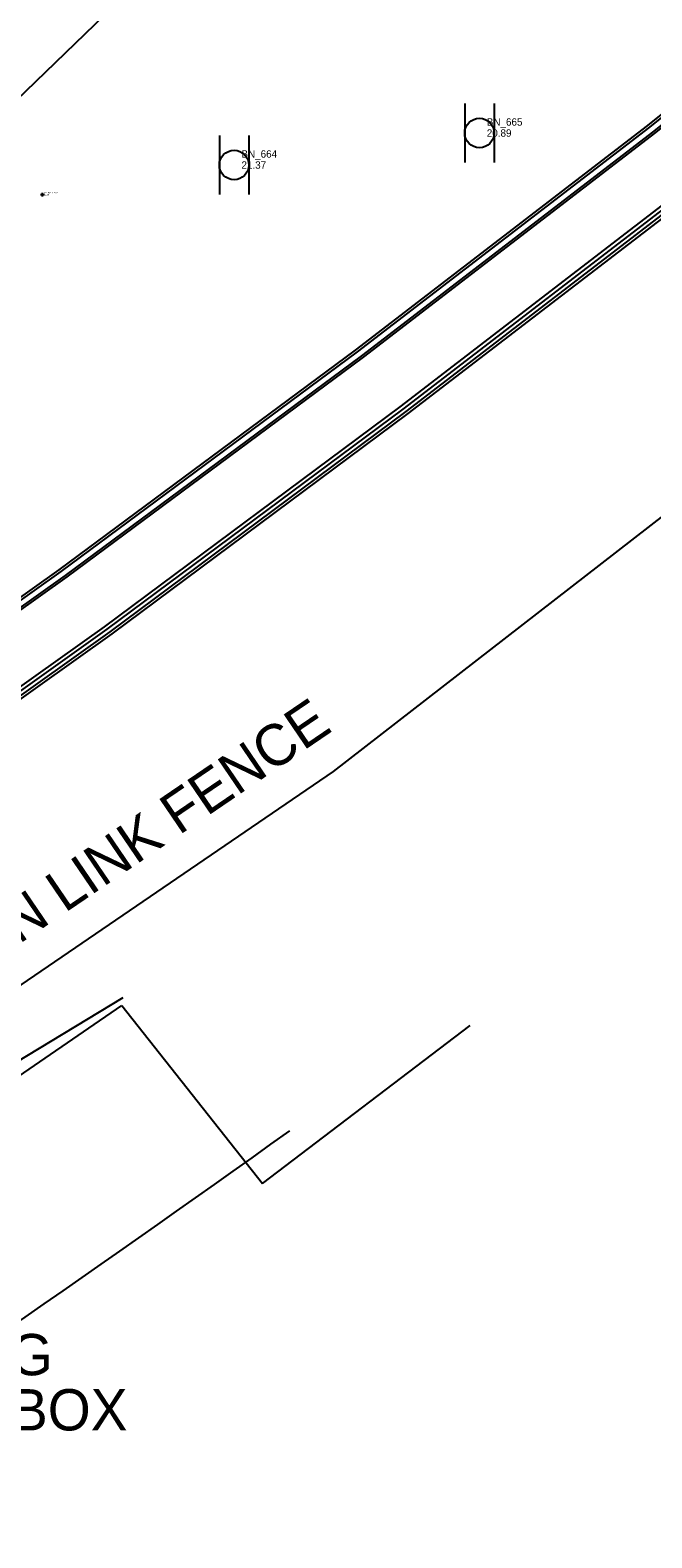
# Model space of a CAD drawing. Extents: x 509744 to 512285, y 1314862 to 1316822.
# Drawn here: x 510576.1 to 510618.3, y 1315900.5 to 1316002.7 of the extents above; entities that cross this region are included whole.
import ezdxf

# ---------------------------------------------------------------- set-up
doc = ezdxf.new("R2010")
doc.units = 0
for name, color, linetype in [('DelineatorPost_ep', 7, 'Continuous'), ('Driveway_ep', 7, 'Continuous'), ('Fence_ep', 7, 'Continuous'), ('GroundShot_ep', 7, 'Continuous'), ('GuardrailLt_ep', 7, 'Continuous'), ('RailroadTracks_ep', 7, 'Continuous'), ('RWLine_ep', 7, 'Continuous'), ('TextElevLabel', 7, 'Continuous'), ('TextPtLabel', 7, 'Continuous'), ('TextTopoLabel_ep', 7, 'Continuous')]:
    doc.layers.add(name, color=color, linetype=linetype)

msp = doc.modelspace()

# ---------------------------------------------------------------- linework, layer by layer
at = {"layer": 'DelineatorPost_ep'}
for p, q in [((510605.57, 1315997.72), (510605.57, 1315993.72)), ((510607.57, 1315997.72), (510607.57, 1315993.72)), ((510588.93, 1315995.55), (510588.93, 1315991.55)), ((510590.93, 1315995.55), (510590.93, 1315991.55))]:
    msp.add_line(p, q, dxfattribs=at)
for centre in [(510606.57, 1315995.72), (510589.93, 1315993.55)]:
    msp.add_circle(centre, 1, dxfattribs=at)
at = {"layer": 'Driveway_ep'}
for p, q in [((510549.36, 1315913.93), (510582.32, 1315936.55)), ((510582.32, 1315936.55), (510591.86, 1315924.48)), ((510591.86, 1315924.48), (510605.94, 1315935.21))]:
    msp.add_line(p, q, dxfattribs=at)
at = {"layer": 'Fence_ep'}
msp.add_lwpolyline([(510688.98, 1316027.04), (510652.22, 1315995.5), (510596.64, 1315952.43), (510538.57, 1315912.77), (510516.68, 1315898.83), (510522.43, 1315839.04)], dxfattribs=at)
at = {"layer": 'GroundShot_ep'}
for p, q in [((510577.05, 1315991.53), (510576.8, 1315991.53)), ((510576.93, 1315991.41), (510576.93, 1315991.66))]:
    msp.add_line(p, q, dxfattribs=at)
at = {"layer": 'GuardrailLt_ep'}
msp.add_lwpolyline([(510555.73, 1315903.14), (510551.51, 1315905.83), (510548.46, 1315913.96), (510558.94, 1315922.9), (510582.41, 1315937.1)], dxfattribs=at)
at = {"layer": 'RailroadTracks_ep'}
for points in [[(510799.57, 1316167.71), (510782.82, 1316149.15), (510765.79, 1316130.85), (510748.4, 1316112.88), (510730.71, 1316095.21), (510712.65, 1316077.9), (510694.36, 1316060.86), (510675.67, 1316044.25), (510656.7, 1316027.86), (510637.45, 1316011.9), (510617.97, 1315996.23), (510598.14, 1315980.99), (510578.04, 1315966.1), (510557.66, 1315951.59), (510537.04, 1315937.41), (510516.18, 1315923.57), (510511.12, 1315920.49)], [(510799.7, 1316167.6), (510782.95, 1316149.03), (510765.92, 1316130.73), (510748.53, 1316112.76), (510730.84, 1316095.09), (510712.78, 1316077.79), (510694.49, 1316060.75), (510675.8, 1316044.14), (510656.82, 1316027.75), (510637.58, 1316011.78), (510618.1, 1315996.11), (510598.27, 1315980.88), (510578.17, 1315965.99), (510557.78, 1315951.47), (510537.17, 1315937.3), (510516.31, 1315923.46), (510511.22, 1315920.36)], [(510800.01, 1316167.33), (510783.25, 1316148.76), (510766.22, 1316130.46), (510748.84, 1316112.49), (510731.15, 1316094.82), (510713.09, 1316077.52), (510694.79, 1316060.48), (510676.11, 1316043.87), (510657.13, 1316027.48), (510637.88, 1316011.51), (510618.4, 1315995.84), (510598.58, 1315980.61), (510578.48, 1315965.72), (510558.09, 1315951.21), (510537.48, 1315937.03), (510516.61, 1315923.19), (510511.44, 1315920.04)], [(510800.11, 1316167.23), (510783.36, 1316148.67), (510766.33, 1316130.37), (510748.94, 1316112.4), (510731.25, 1316094.73), (510713.19, 1316077.43), (510694.9, 1316060.39), (510676.21, 1316043.78), (510657.24, 1316027.38), (510637.99, 1316011.42), (510618.51, 1315995.75), (510598.68, 1315980.52), (510578.58, 1315965.63), (510558.2, 1315951.11), (510537.58, 1315936.94), (510516.72, 1315923.1), (510511.51, 1315919.92)], [(510803.2, 1316164.29), (510786.44, 1316145.73), (510769.41, 1316127.43), (510752.02, 1316109.46), (510734.06, 1316091.52), (510716, 1316074.21), (510697.7, 1316057.17), (510679.02, 1316040.56), (510659.79, 1316023.96), (510640.55, 1316008), (510621.01, 1315992.4), (510601.18, 1315977.16), (510581.11, 1315962.24), (510560.6, 1315947.62), (510539.99, 1315933.45), (510519.13, 1315919.61), (510511.24, 1315914.78)], [(510803.39, 1316164.12), (510786.63, 1316145.56), (510769.6, 1316127.26), (510752.21, 1316109.29), (510734.25, 1316091.35), (510716.19, 1316074.05), (510697.89, 1316057), (510679.21, 1316040.39), (510659.98, 1316023.79), (510640.74, 1316007.83), (510621.2, 1315992.23), (510601.37, 1315977), (510581.3, 1315962.07), (510560.79, 1315947.46), (510540.18, 1315933.28), (510519.32, 1315919.44), (510511.35, 1315914.56)], [(510803.58, 1316163.95), (510786.82, 1316145.39), (510769.79, 1316127.09), (510752.41, 1316109.12), (510734.44, 1316091.18), (510716.38, 1316073.88), (510698.09, 1316056.83), (510679.4, 1316040.22), (510660.18, 1316023.62), (510640.93, 1316007.66), (510621.4, 1315992.06), (510601.57, 1315976.83), (510581.5, 1315961.9), (510560.99, 1315947.29), (510540.37, 1315933.11), (510519.51, 1315919.27), (510511.45, 1315914.33)], [(510803.74, 1316163.81), (510786.98, 1316145.25), (510769.95, 1316126.95), (510752.56, 1316108.98), (510734.6, 1316091.04), (510716.54, 1316073.74), (510698.24, 1316056.7), (510679.56, 1316040.08), (510660.33, 1316023.48), (510641.09, 1316007.52), (510621.55, 1315991.92), (510601.72, 1315976.69), (510581.65, 1315961.76), (510561.14, 1315947.15), (510540.53, 1315932.97), (510519.67, 1315919.13), (510511.53, 1315914.16)]]:
    msp.add_lwpolyline(points, dxfattribs=at)
at = {"layer": 'RWLine_ep'}
msp.add_line((510616.27, 1316037.67), (510510.67, 1315935.62), dxfattribs=at)
msp.add_arc((509687.45, 1317196.75), 1559.13, 301.85281, 305.53896, dxfattribs=at)

# ---------------------------------------------------------------- texts
at = {"layer": 'TextElevLabel'}
for s, height, p in [('20.89', 0.5, (510607.07, 1315995.47)), ('21.37', 0.5, (510590.43, 1315993.3)), ('21.29', 0.1, (510577.03, 1315991.48))]:
    msp.add_text(s, height=height, dxfattribs=at).set_placement(p)
at = {"layer": 'TextPtLabel'}
for s, height, p in [('BN_665', 0.5, (510607.07, 1315996.22)), ('BN_664', 0.5, (510590.43, 1315994.05)), ('DEFAULT_619', 0.1, (510577.03, 1315991.63))]:
    msp.add_text(s, height=height, dxfattribs=at).set_placement(p)
at = {"layer": 'TextTopoLabel_ep'}
msp.add_text('6 FT CHAIN LINK FENCE', height=2.8, rotation=34.2256, dxfattribs=at).set_placement((510560.73, 1315930.75))
for s, p in [('R/R XING', (510561, 1315911.48)), ('CONTROL BOX', (510555.45, 1315907.74))]:
    msp.add_text(s, height=2.8, dxfattribs=at).set_placement(p)

doc.saveas('drawing.dxf')
